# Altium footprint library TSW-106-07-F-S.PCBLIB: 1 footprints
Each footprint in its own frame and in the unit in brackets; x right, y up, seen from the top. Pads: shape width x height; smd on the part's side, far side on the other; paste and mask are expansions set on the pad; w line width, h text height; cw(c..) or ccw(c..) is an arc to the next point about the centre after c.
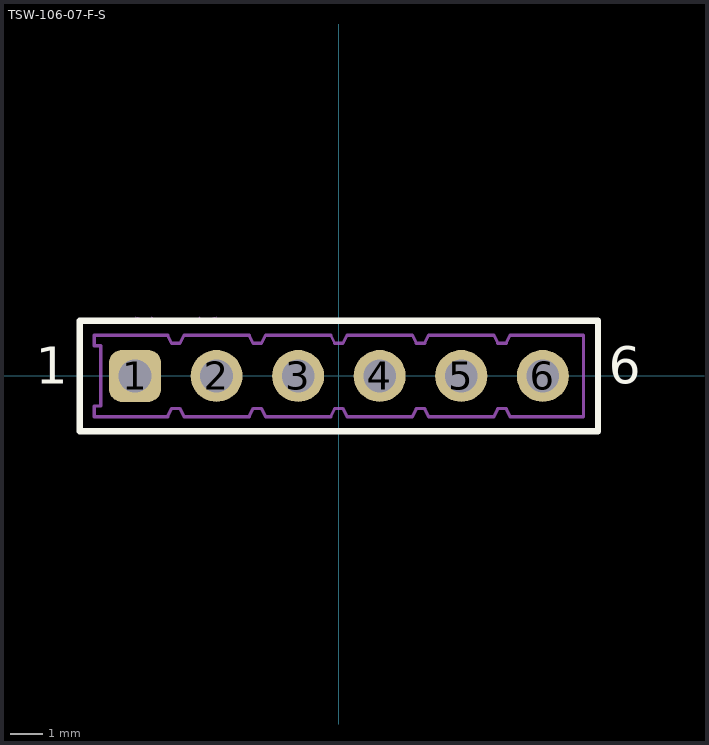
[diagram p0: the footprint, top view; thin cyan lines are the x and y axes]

## TSW-106-07-F-S [mm]
pads (6):
  rrect50% 1.62x1.62 hole 1.02: 1(-6.35,0)
  round 1.62 hole 1.02: 2(-3.81,0) 3(-1.27,0) 4(1.27,0) 5(3.81,0) 6(6.35,0)
Top Overlay:
  lines w0.2: -8.07,-1.72 -8.07,1.72 8.07,1.72 8.07,-1.72 -8.07,-1.72
  text "6" at 8.411,-0.635 h1.97
  text "1" at -9.44,-0.635 h1.97
Top Solder:
  circle w0: c6.35,0 r0.861
  circle w0: c3.81,0 r0.861
  circle w0: c1.27,0 r0.861
  circle w0: c-1.27,0 r0.861
  circle w0: c-3.81,0 r0.861
  circle w0: c-6.35,0 r0.861
Bottom Solder:
  circle w0: c6.35,0 r0.861
  circle w0: c3.81,0 r0.861
  circle w0: c1.27,0 r0.861
  circle w0: c-1.27,0 r0.861
  circle w0: c-3.81,0 r0.861
  circle w0: c-6.35,0 r0.861
Mechanical 16:
  lines w0.1: -7.62,-1.27 -5.334,-1.27 -5.21,-1.016 -5.08,-1.016 -4.95,-1.016 -4.826,-1.27 -2.794,-1.27 -2.67,-1.016 -2.54,-1.016 -2.41,-1.016 -2.286,-1.27 -0.254,-1.27 -0.13,-1.016 0,-1.016 0.13,-1.016 0.254,-1.27 2.286,-1.27 2.41,-1.016 2.54,-1.016 2.67,-1.016 2.794,-1.27 4.826,-1.27 4.95,-1.016 5.08,-1.016 5.21,-1.016 5.334,-1.27 7.62,-1.27 7.62,1.27 5.334,1.27 5.21,1.016 5.08,1.016 4.95,1.016 4.826,1.27 2.794,1.27 2.67,1.016 2.54,1.016 2.41,1.016 2.286,1.27 0.254,1.27 0.13,1.016 0,1.016 -0.13,1.016 -0.254,1.27 -2.286,1.27 -2.41,1.016 -2.54,1.016 -2.67,1.016 -2.794,1.27 -4.826,1.27 -4.95,1.016 -5.08,1.016 -5.21,1.016 -5.334,1.27 -7.62,1.27 -7.62,0.94 -7.417,0.94 -7.417,-0.94 -7.62,-0.94 -7.62,-1.27 ; -6.668,-0.318 -6.032,-0.318 -6.032,0.318 -6.668,0.318 -6.668,-0.318 ; -4.128,-0.318 -3.492,-0.318 -3.492,0.318 -4.128,0.318 -4.128,-0.318 ; -1.588,-0.318 -0.952,-0.318 -0.952,0.318 -1.588,0.318 -1.588,-0.318 ; 0.952,-0.318 1.588,-0.318 1.588,0.318 0.952,0.318 0.952,-0.318 ; 3.492,-0.318 4.128,-0.318 4.128,0.318 3.492,0.318 3.492,-0.318 ; 6.032,-0.318 6.668,-0.318 6.668,0.318 6.032,0.318 6.032,-0.318
  text "6" at 8.411,-0.635 h1.97
  text "1" at -9.44,-0.635 h1.97
Mechanical 40:
  lines w0: -6.35,1.842 -5.715,1.683 -5.842,1.842 ; -4.382,1.762 -4.445,1.683 ; -4.318,1.842 -4.445,1.683 ; -3.81,1.842 -4.445,1.683
Mechanical 42:
  lines w0.1: -8.07,-1.72 -8.07,1.72 8.07,1.72 8.07,-1.72 -8.07,-1.72
3D body "TSW-106-07-F-S.stp": height 8.38, standoff -2.54, extent -7.747,-1.27 7.62,1.27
